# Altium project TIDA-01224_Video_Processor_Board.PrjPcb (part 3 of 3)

## Sheet TIDA-010224_Video_Processor_P04_Peripherals.SchDoc: TIDA-010224_P04_Peripherals
size A2; Date: Not shown in title block; ApprovedBy: Not shown in title block; CheckedBy: Not shown in title block; Author: Not shown in title block; CompanyName: Not shown in title block; DrawnBy: Sakshi Markhedkar; Engineer: Not shown in title block; Organization: Not shown in title block; Address1: Not shown in title block; Address2: Not shown in title block; Address3: Not shown in title block; Address4: Not shown in title block; DocumentNumber: 5; Revision: Use project parameter SCH_Rev; SheetNumber: 5; SheetTotal: 6; PageSetup: Record=PageOptions¦CenterHorizontal=True¦CenterVertical=True¦PrintScale=1.00¦XCorrection=1.00¦YCorrection=1.00¦PrintKind=0¦BorderSize=5000000¦LeftOffset=0¦BottomOffset=0¦Orientation=2¦PaperLength=1000¦PaperWidth=1000¦Scale=100¦PaperSource=15¦PrintQuality=600¦MediaType=1¦DitherType=10¦PaperKind=Letter¦PrintScaleMode=1
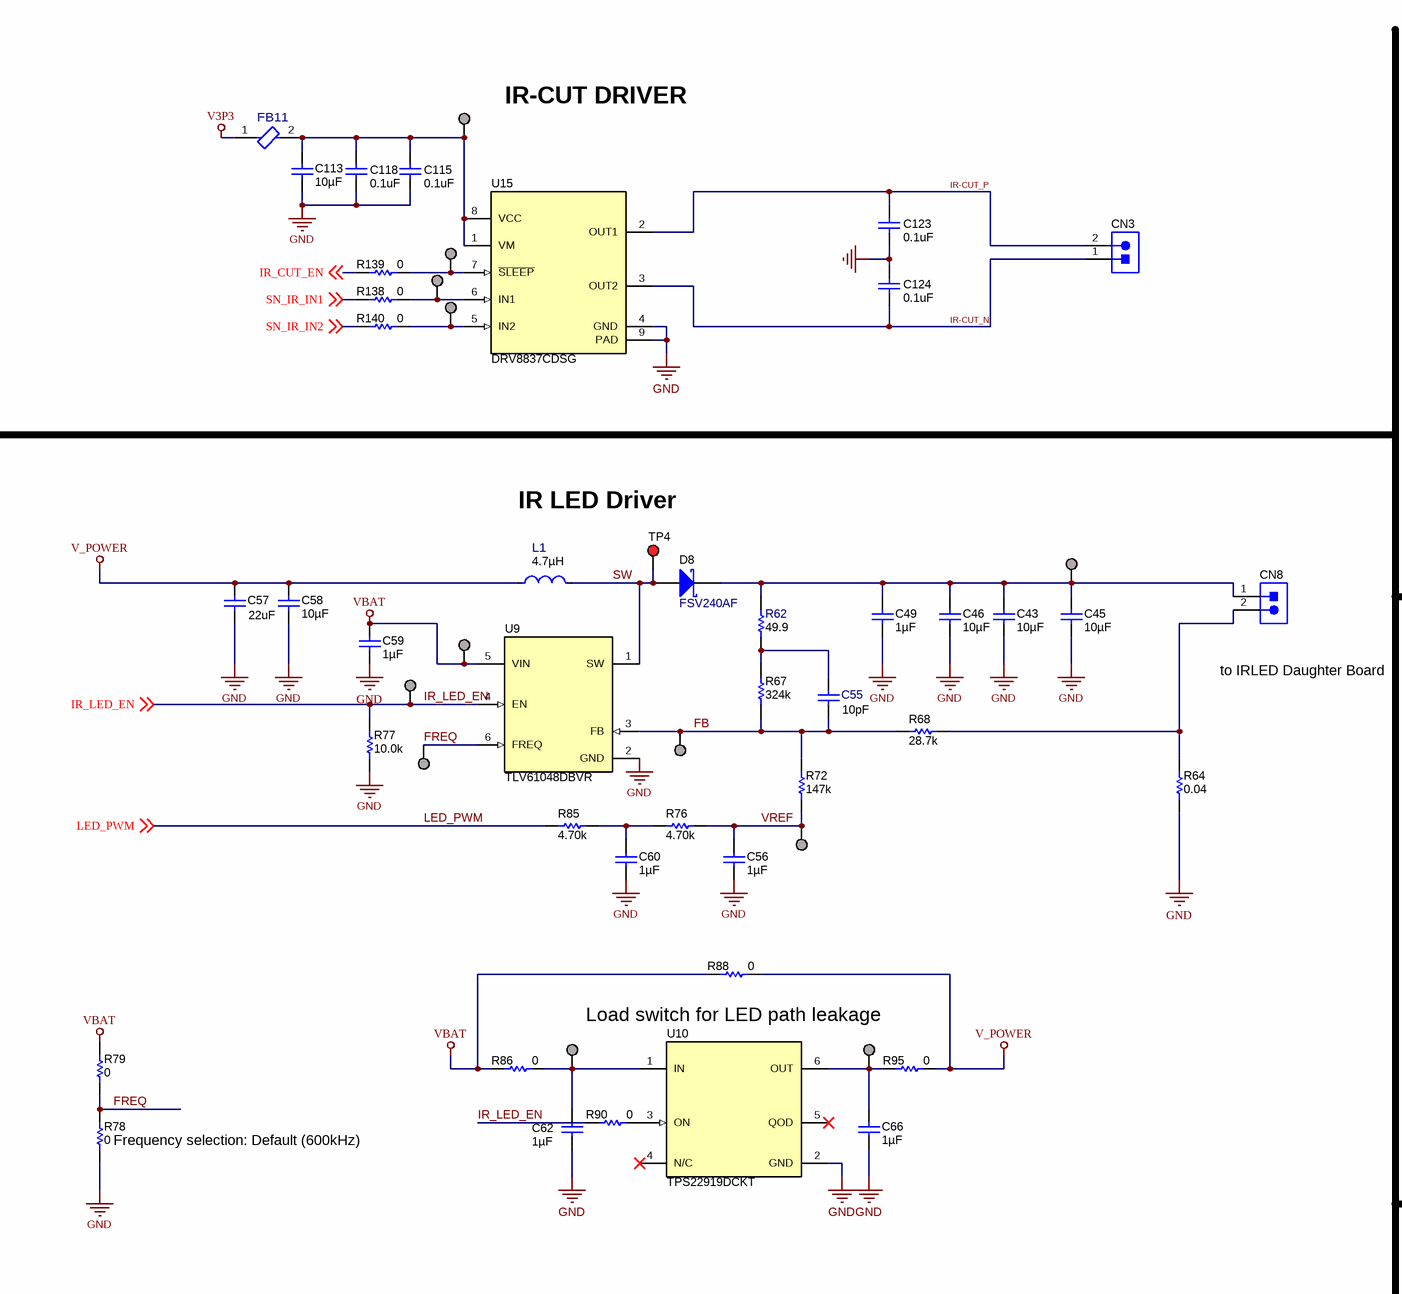
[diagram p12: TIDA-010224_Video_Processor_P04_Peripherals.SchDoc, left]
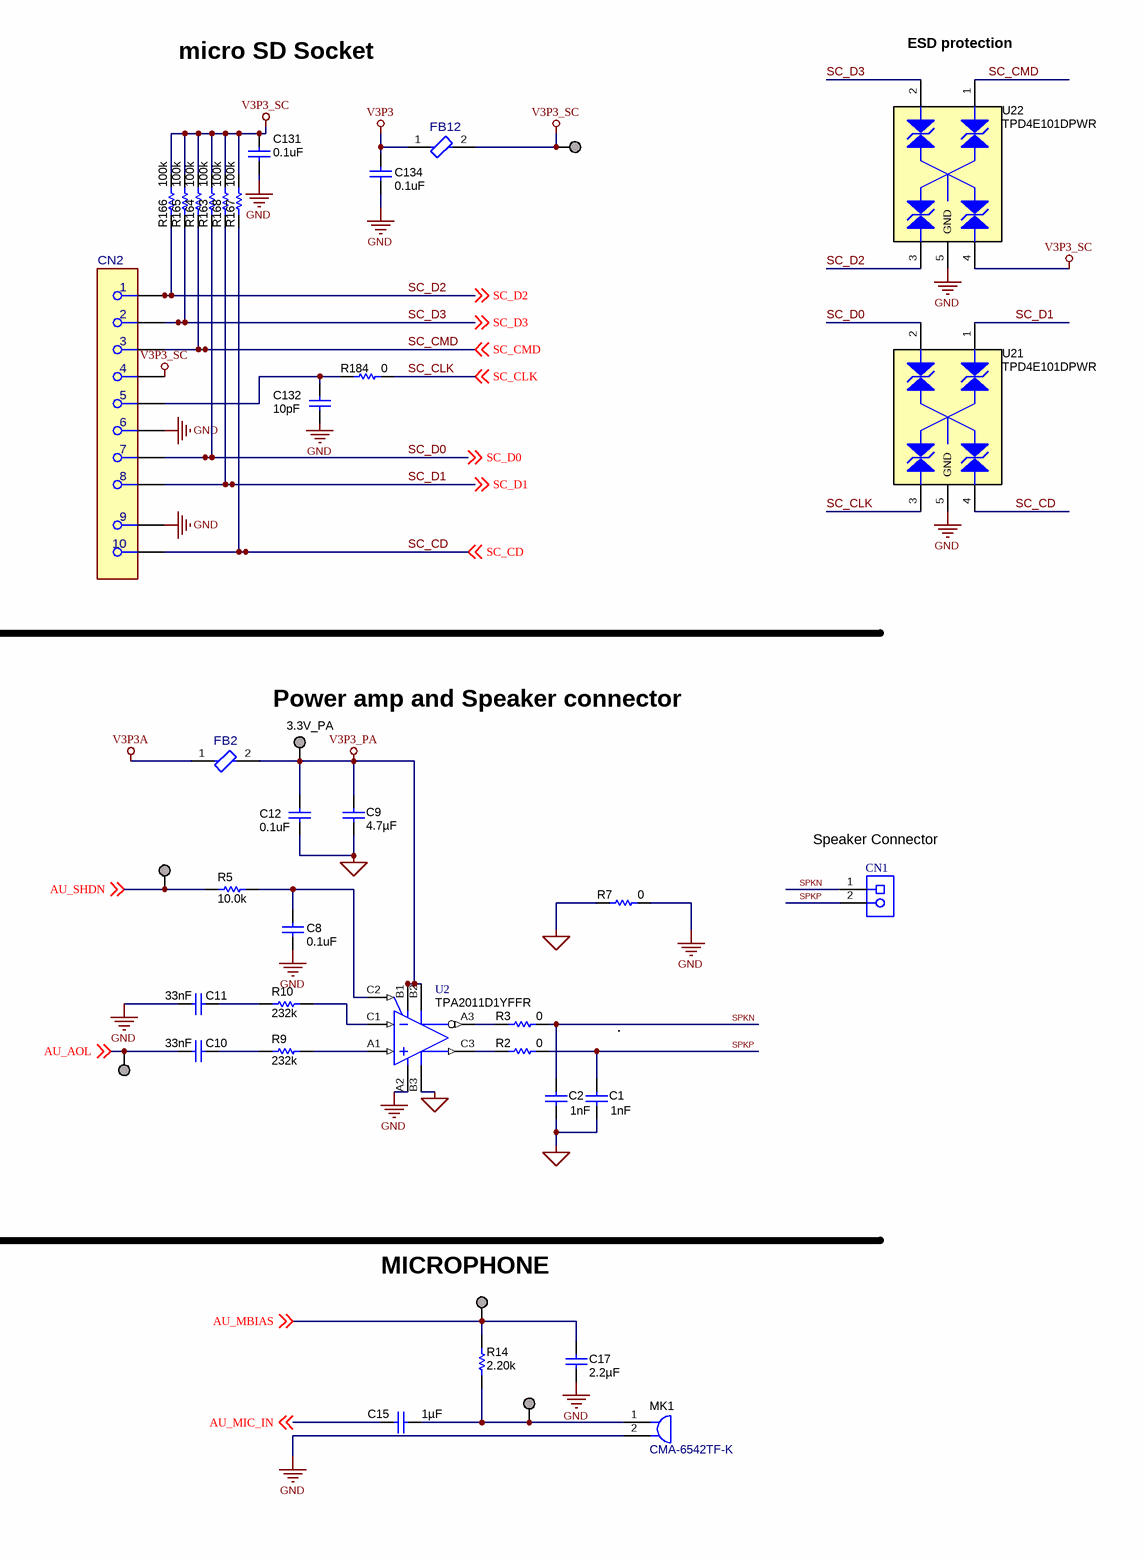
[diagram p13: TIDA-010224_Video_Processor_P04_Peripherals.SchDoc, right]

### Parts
3.3V_PA  RCU-0C  [TE_RCU]  (value not drawn)
3.3V_SC  TP_SM_1MM  [TP_SM_1MM]  (value not drawn)  (no BOM)
AOL  TP_SM_1MM  [TP_SM_1MM]  (value not drawn)  (no BOM)
C1  Cap_F: 1nF  [0402]  (hidden comment: GRM155R71C102KA01D)
C2  Cap_F: 1nF  [0402]  (hidden comment: GRM155R71C102KA01D)
C8  value 0.1uF  [0402]  (hidden comment: GRM155R71C104KA88D)
C9  Cap_F: 4.7µF  [0603]  (hidden comment: GRM188Z71C475KE21D)
C10  Cap_F: 33nF  [0402]  (hidden comment: GRM155R71C333KA01D)
C11  Cap_F: 33nF  [0402]  (hidden comment: GRM155R71C333KA01D)
C12  value 0.1uF  [0402]  (hidden comment: GRM155R71C104KA88D)
C15  Cap_F: 1µF  [0603]  (hidden comment: GCM188R71C105MA64D)
C17  Cap_F: 2.2µF  [0603]  (hidden comment: GRM188Z71C225KE43)
C43  Cap_F: 10µF  [0805_HV]  (hidden comment: CL21B106KOQNNNE)
C45  Cap_F: 10µF  [0805_HV]  (hidden comment: CL21B106KOQNNNE)
C46  Cap_F: 10µF  [0805_HV]  (hidden comment: CL21B106KOQNNNE)
C49  Cap_F: 1µF  [0603]  (hidden comment: GCM188R71C105MA64D)
C55  Cap_F: 10pF  [0402]  (hidden comment: GRM1555C1H100FA01D)
C56  Cap_F: 1µF  [0603]  (hidden comment: GCM188R71C105MA64D)
C57  ValueDisplayed: 22uF  [1210_280]  (hidden comment: CGA6P1X7R1C226M250AC)
C58  Cap_F: 10µF  [0805_HV]  (hidden comment: CL21B106KOQNNNE)
C59  Cap_F: 1µF  [0603]  (hidden comment: GCM188R71C105MA64D)
C60  Cap_F: 1µF  [0603]  (hidden comment: GCM188R71C105MA64D)
C62  Cap_F: 1µF  [0603]  (hidden comment: GCM188R71C105MA64D)
C66  Cap_F: 1µF  [0603]  (hidden comment: GCM188R71C105MA64D)
C113  Cap_F: 10µF  [0805_HV]  (hidden comment: CL21B106KOQNNNE)
C115  value 0.1uF  [0402]
C118  value 0.1uF  [0402]
C123  value 0.1uF  [0402]
C124  value 0.1uF  [0402]
C131  value 0.1uF  [0402]  (hidden comment: GRM155R71C104KA88D)
C132  ValueDisplayed: 10pF  [0402]  (hidden comment: 885012005055)
C134  value 0.1uF  [0402]  (hidden comment: GRM155R71C104KA88D)
CN1  282834-2  [TEC_282834-2]  (value not drawn)
CN2  693071010811  [FP-693071010811_CONN_SMT_MEMORY-MFG]  (value not drawn)
CN3  53398-0271  [0533980271]  (value not drawn)
CN8  PEC01DAAN  [Sullins_PxC01DAAN]  (value not drawn)
D8  FSV240AF  [SMAF]
FB  TP_SM_1MM  [TP_SM_1MM]  (value not drawn)  (no BOM)
FB2  BLM18KG121TN1D  [FP-BLM18KG121TN1D_0603-MFG]  (value not drawn)
FB11  BLM18KG121TN1D  [FP-BLM18KG121TN1D_0603-MFG]  (value not drawn)
FB12  BLM18KG121TN1D  [FP-BLM18KG121TN1D_0603-MFG]  (value not drawn)
FREQ  TP_SM_1MM  [TP_SM_1MM]  (value not drawn)  (no BOM)
IN_PS  TP_SM_1MM  [TP_SM_1MM]  (value not drawn)  (no BOM)
IR_EN  TP_SM_1MM  [TP_SM_1MM]  (value not drawn)  (no BOM)
IR_IN1  TP_SM_1MM  [TP_SM_1MM]  (value not drawn)  (no BOM)
IR_IN2  TP_SM_1MM  [TP_SM_1MM]  (value not drawn)  (no BOM)
L1  Ind_H: 4.7µH  [FP-XAL4030-472MEC_SMD2-MFG]  (hidden comment: XAL4030-472MEC)
LED_EN  TP_SM_1MM  [TP_SM_1MM]  (value not drawn)  (no BOM)
LED_OUT  TP_SM_1MM  [TP_SM_1MM]  (value not drawn)  (no BOM)
MBIAS  TP_SM_1MM  [TP_SM_1MM]  (value not drawn)  (no BOM)
MIC_IN  TP_SM_1MM  [TP_SM_1MM]  (value not drawn)  (no BOM)
MK1  CMA-6542TF-K  [CUI_CMA-6542TF-K]
OUT_PS  TP_SM_1MM  [TP_SM_1MM]  (value not drawn)  (no BOM)
R2  ValueDisplayed: 0  [0603]  (hidden comment: RMCF0603ZT0R00)
R3  ValueDisplayed: 0  [0603]  (hidden comment: RMCF0603ZT0R00)
R5  ValueDisplayed: 10.0k  [0402]  (hidden comment: ERJPA2F1002X)
R7  ValueDisplayed: 0  [0402S]  (hidden comment: RC0402JR-070RL)
R9  ValueDisplayed: 232k  [0402]  (hidden comment: RC1005F2323CS)
R10  ValueDisplayed: 232k  [0402]  (hidden comment: RC1005F2323CS)
R14  ValueDisplayed: 2.20k  [0402]  (hidden comment: ERA2AEB222X)
R62  ValueDisplayed: 49.9  [0603]  (hidden comment: CRCW060349R9FKEA)
R64  ValueDisplayed: 0.04  [2010]  (hidden comment: CSRN2010FK40L0)
R67  ValueDisplayed: 324k  [0603]  (hidden comment: RC0603FR-07324KL)
R68  ValueDisplayed: 28.7k  [0603]  (hidden comment: CRCW060328K7FKEA)
R72  ValueDisplayed: 147k  [0603]  (hidden comment: CRCW0603147KFKEA)
R76  ValueDisplayed: 4.70k  [0402]  (hidden comment: ERJ-2RKF4701X)
R77  ValueDisplayed: 10.0k  [0402]  (hidden comment: ERJPA2F1002X)
R78  ValueDisplayed: 0  [0402S]  (hidden comment: RC0402JR-070RL)
R79  ValueDisplayed: 0  [0402S]  (hidden comment: RC0402JR-070RL)
R85  ValueDisplayed: 4.70k  [0402]  (hidden comment: ERJ-2RKF4701X)
R86  ValueDisplayed: 0  [0603]  (hidden comment: RMCF0603ZT0R00)
R88  ValueDisplayed: 0  [0603]  (hidden comment: RMCF0603ZT0R00)
R90  ValueDisplayed: 0  [0402S]  (hidden comment: RC0402JR-070RL)
R95  ValueDisplayed: 0  [0603]  (hidden comment: RMCF0603ZT0R00)
R138  ValueDisplayed: 0  [0402S]  (hidden comment: RC0402JR-070RL)
R139  ValueDisplayed: 0  [0402S]  (hidden comment: RC0402JR-070RL)
R140  ValueDisplayed: 0  [0402S]  (hidden comment: RC0402JR-070RL)
R163  ValueDisplayed: 100k  [0201]  (hidden comment: RC0201FR-07100KL)
R164  ValueDisplayed: 100k  [0201]  (hidden comment: RC0201FR-07100KL)
R165  ValueDisplayed: 100k  [0201]  (hidden comment: RC0201FR-07100KL)
R166  ValueDisplayed: 100k  [0201]  (hidden comment: RC0201FR-07100KL)
R167  ValueDisplayed: 100k  [0201]  (hidden comment: RC0201FR-07100KL)
R168  ValueDisplayed: 100k  [0201]  (hidden comment: RC0201FR-07100KL)
R184  ValueDisplayed: 0  [0402S]  (hidden comment: RC0402JR-070RL)
REF  TP_SM_1MM  [TP_SM_1MM]  (value not drawn)  (no BOM)
SHDN  TP_SM_1MM  [TP_SM_1MM]  (value not drawn)  (no BOM)
TP4  Bias  [Keystone5000]  (value not drawn)
U2  TPA2011D1YFFR  [YFF0009AAAC]
U9  TLV61048DBVR  [DBV0006A_N]
U10  TPS22919DCKT  [DCK0006A_N]
U15  DRV8837CDSG  [DSG0008A]
U21  TPD4E101DPWR  [DPW0004A]
U22  TPD4E101DPWR  [DPW0004A]
VCC_IR  TP_SM_1MM  [TP_SM_1MM]  (value not drawn)  (no BOM)
VP  TP_SM_1MM  [TP_SM_1MM]  (value not drawn)  (no BOM)

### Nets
AGND: C1.2 C2.2 C9.2 C12.1 R7.1 U2.B3(PGND)
GND: C8.1 C11.2 C17.1 C43.2 C45.2 C46.2 C49.1 C56.1 C57.2 C58.2 C59.1 C60.1 C62.2 C66.2 C113.2 C115.1 C118.1 C123.1 C124.2 C131.1 C132.2 C134.1 CN2.6 CN2.9 MK1.2 R7.2 R64.1 R77.1 R78.1 U2.A2(GND) U9.2(GND) U10.2(GND) U15.4(GND) U15.9(PAD) U21.5(GND) U22.5(GND)
V3P3: C134.2 FB11.1 FB12.1
V3P3_PA: 3.3V_PA.1 C9.1 C12.2 FB2.2 U2.B1(VDD) U2.B2(PVDD)
V3P3_SC: 3.3V_SC.1 C131.2 CN2.4 FB12.2 R163.2 R164.2 R165.2 R166.2 R167.2 R168.2 U22.4
V3P3A: FB2.1
V_POWER: C57.1 C58.1 L1.1 R88.2 R95.2
VBAT: C59.2 R79.2 R86.1 R88.1 U9.5(VIN) VP.1
AU_AOL: AOL.1 C10.2 ; off-sheet AU_AOL
AU_MBIAS: C17.2 MBIAS.1 R14.2 ; off-sheet AU_MBIAS
AU_MIC_IN: C15.1 ; off-sheet AU_MIC_IN
AU_SHDN: R5.1 SHDN.1 ; off-sheet AU_SHDN
FB: C55.2 FB.1 R67.1 R68.1 R72.2 U9.3(FB)
FREQ: FREQ.1 R78.2 R79.1 U9.6(FREQ)
IR-CUT_N: C124.1 CN3.1 U15.3(OUT2)
IR-CUT_P: C123.2 CN3.2 U15.2(OUT1)
IR_CUT_EN: R139.1 ; off-sheet IR_CUT_EN
IR_LED_EN: LED_EN.1 R77.2 R90.1 U9.4(EN) ; off-sheet IR_LED_EN
LED_PWM: R85.1 ; off-sheet LED_PWM
SC_CD: CN2.10 R167.1 U21.4 ; off-sheet SC_CD
SC_CLK: R184.2 U21.3 ; off-sheet SC_CLK
SC_CMD: CN2.3 R164.1 U22.1 ; off-sheet SC_CMD
SC_D0: CN2.7 R163.1 U21.2 ; off-sheet SC_D0
SC_D1: CN2.8 R168.1 U21.1 ; off-sheet SC_D1
SC_D2: CN2.1 R166.1 U22.3 ; off-sheet SC_D2
SC_D3: CN2.2 R165.1 U22.2 ; off-sheet SC_D3
SN_IR_IN1: R138.1 ; off-sheet SN_IR_IN1
SN_IR_IN2: R140.1 ; off-sheet SN_IR_IN2
SPKN: C2.1 CN1.1 R3.2
SPKP: C1.1 CN1.2 R2.2
SW: D8.2(A) L1.2 TP4.1 U9.1(SW)
VREF: C56.2 R72.1 R76.2 REF.1
NetC8_2: C8.2 R5.2 U2.C2(EN)
NetC10_1: C10.1 R9.1
NetC11_1: C11.1 R10.1
NetC15_2: C15.2 MIC_IN.1 MK1.1 R14.1
NetC43_1: C43.1 C45.1 C46.1 C49.2 CN8.1 D8.1(K) LED_OUT.1 R62.2
NetC55_1: C55.1 R62.1 R67.2
NetC60_2: C60.2 R76.1 R85.2
NetC62_1: C62.1 IN_PS.1 R86.2 U10.1(IN)
NetC66_1: C66.1 OUT_PS.1 R95.1 U10.6(OUT)
NetC113_1: C113.1 C115.2 C118.2 FB11.2 U15.1(VM) U15.8(VCC) VCC_IR.1
NetC132_1: C132.1 CN2.5 R184.1
NetCN8_2: CN8.2 R64.2 R68.2
NetIR_EN_1: IR_EN.1 R139.2 U15.7(~{SLEEP})
NetIR_IN1_1: IR_IN1.1 R138.2 U15.6(IN1)
NetIR_IN2_1: IR_IN2.1 R140.2 U15.5(IN2)
NetR2_1: R2.1 U2.C3(VO+)
NetR3_1: R3.1 U2.A3(VO-)
NetR9_2: R9.2 U2.A1(IN+)
NetR10_2: R10.2 U2.C1(IN-)
NetR90_2: R90.2 U10.3(ON)

Not connected (* = marked no-connect by the designer): U10 4(N/C)* 5(QOD)*

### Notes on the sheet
- micro SD Socket
- ESD protection
- (near VCC_IR) IR-CUT DRIVER
- (near TP4) IR LED Driver
- to IRLED Daughter Board
- (near 3.3V_PA) Power amp and Speaker connector
- (near CN1) Speaker Connector
- Load switch for LED path leakage
- (near R78) Frequency selection: Default (600kHz)
- (near MBIAS) MICROPHONE

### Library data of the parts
3.3V_PA = CMP-0067620-1: PC Test Point, SMT; Manufacturer: TE Connectivity
3.3V_SC AOL FB FREQ IN_PS IR_EN IR_IN1 IR_IN2 LED_EN LED_OUT MBIAS MIC_IN OUT_PS REF SHDN VCC_IR VP = CMP-0003825-1: 1mm Test Point, SMT; Manufacturer: Any
C1 C2 = CMP-0006638-2: CAP, CERM, 1000 pF, 16 V, +/- 10%, X7R, 0402; Manufacturer: MuRata; TaMin_C: -55°C; Polarized: N; SizeAreaWB_mm2: 3; Value1: Unknown; U/M: EA; Value: 1000pF; TaMax_C: 125°C; SizeZ_mm: 0.6; SizeX_mm: 1; SizeY_mm: 0.5; Value2: 16V; AEC Category: Q200
C8 C12 C131 C134 = Cap: CAP CER 0.1UF 16V 10% X7R 0402; Manufacturer: Murata Electronics North America
C9 = CMP-0064936-4: CAP, CERM, 4.7 uF, 16 V,+/- 10%, X7R, 0603; Manufacturer: MuRata; TaMin_C: -55°C; Polarized: N; SizeAreaWB_mm2: 4.68; Value1: Unknown; U/M: EA; Value: 4.7uF; TaMax_C: 125°C; SizeZ_mm: 1; SizeX_mm: 1.6; SizeY_mm: 0.8; Value2: 16V; SizeArea_mm2: 1.28; AEC Category: Q200
C10 C11 = CMP-0006650-2: CAP, CERM, 0.033 uF, 16 V, +/- 10%, X7R, 0402; Manufacturer: MuRata; TaMin_C: -55°C; Polarized: N; SizeAreaWB_mm2: 3; Value1: Unknown; U/M: EA; TaMax_C: 125°C; SizeZ_mm: 0.6; SizeX_mm: 1; SizeY_mm: 0.5; Value2: 16V; AEC Category: Q200
C15 C49 C56 C59 C60 C62 C66 = CMP-0007137-1: CAP, CERM, 1 uF, 16 V, +/- 20%, X7R, AEC-Q200 Grade 1, 0603; Manufacturer: MuRata; TaMin_C: -55°C; Polarized: N; SizeAreaWB_mm2: 4.68; Value1: Unknown; U/M: EA; Value: 1uF; TaMax_C: 125°C; SizeZ_mm: 1; SizeX_mm: 1.6; SizeY_mm: 0.8; Value2: 16V; SizeArea_mm2: 1.28; AEC Qualified: Y; AEC Category: Q200
C17 = CMP-0007499-1: CAP, CERM, 2.2 uF, 16 V, +/- 10%, X7R, 0603; Manufacturer: MuRata; TaMin_C: -55°C; Polarized: N; SizeAreaWB_mm2: 4.68; Value1: Unknown; U/M: EA; Value: 2.2uF; TaMax_C: 125°C; SizeZ_mm: 1; SizeX_mm: 1.6; SizeY_mm: 0.8; Value2: 16V; SizeArea_mm2: 1.28; AEC Category: Q200
C43 C45 C46 C58 C113 = CMP-0007995-1: CAP, CERM, 10 uF, 16 V, +/- 10%, X7R, 0805; Manufacturer: Samsung Electro-Mechanics; TaMin_C: -55°C; Polarized: N; SizeAreaWB_mm2: 6.75; Value1: Unknown; U/M: EA; Value: 10uF; TaMax_C: 125°C; SizeZ_mm: 1.45; SizeX_mm: 2; SizeY_mm: 1.25; Cap_Case: 0805; Value2: 16V; SizeArea_mm2: 2.5; AEC Category: Q200
C55 = CMP-0064916-2: CAP, CERM, 10 pF, 50 V,+/- 1%, C0G/NP0, 0402; Manufacturer: MuRata; TaMin_C: -55°C; Polarized: N; SizeAreaWB_mm2: 3; Value1: Unknown; U/M: EA; Value: 10pF; TaMax_C: 125°C; SizeZ_mm: 0.6; SizeX_mm: 1; SizeY_mm: 0.5; Value2: 50V; AEC Category: Q200
C57 = CMP-0009154-2: CAP, CERM, 22 uF, 16 V, +/- 20%, X7R, AEC-Q200 Grade 1, 1210; Manufacturer: TDK; TaMin_C: -55°C; ESR_ohm: 2.582m; Polarized: N; SizeAreaWB_mm2: 14.7; Value1: 0.002582 ohm; U/M: EA; Value: 22uF; TaMax_C: 125°C; SizeZ_mm: 2.8; SizeX_mm: 3.2; SizeY_mm: 2.5; Value2: 16V; SizeArea_mm2: 8; AEC Qualified: Y; Cap_F: 22µF; IRMS_A: 4.57562A; AEC Grade: 1; AEC Category: Q200
C115 C118 C123 C124 = Cap: CAP CER 0.1UF 16V 10% X7R 0402; Manufacturer: Murata Electronics North America; MFG Part Number: GRM155R71C104KA88D
C132 = CMP-0006215-2: CAP, CERM, 10 pF, 50 V, +/- 5%, C0G/NP0, 0402; Manufacturer: Wurth Elektronik; TaMin_C: -55°C; Polarized: N; SizeAreaWB_mm2: 3; Value1: Unknown; U/M: EA; Value: 10pF; TaMax_C: 125°C; SizeZ_mm: 0.6; SizeX_mm: 1; SizeY_mm: 0.5; Value2: 50V; AEC Category: Q200
CN1 = CMP-0054974-1: Terminal Block, 2x1, 2.54mm, TH; Manufacturer: TE Connectivity; CNHeader: FALSE; Green_Lifecycle: Active; Green_REACh: Passed; CT: TRUE
CN2 = CMP-0089421-1: 9 (8 + 1) Position Card Connector Secure Digital - microSD™ Surface Mount, Right Angle Gold; Manufacturer: Wurth Electronics; DUT-Pitch_mm: 1.1mm; Conn Orientation: Horizontal; Is Female: yes; AEC Qualified: No; Voltage_V: 100V; SizeZ_mm: 2.13mm; Memory Type: FLASH; Current_A: 500mA
CN3 = CMP-0055117-1: Plug, SMT, Vertical, 1.25mm, 1x2; Manufacturer: Molex; CT: FALSE; CompType: Header
CN8 = CMP-0054594-1: Header, 2.54mm, 1x2, Tin, Black, TH; Manufacturer: Sullins Connector Solutions; CNHeader: TRUE; Current_A: 3A; Green_Lifecycle: Active; Shrouded: N; Gender: Male; Green_REACh: Passed; Voltage_V: 1.8kV; Row_Count: 2; RowSpacing_mm: 2.54; CT: FALSE; Cert_UL: Y
D8 = CMP-0028822-2: Diode, Schottky, 40 V, 2 A, AEC-Q101, SMAF; Manufacturer: Fairchild Semiconductor; AEC Category: Q101; SizeArea_mm2: 11.75; Vr_V: 40V; TJmax_C: 150°C; SizeY_mm: 2.5; Green_REACh: Incomplete; Io_A: 2A; SizeX_mm: 4.7; AEC Qualified: Y; Green_Lifecycle: Not Set; Value: 40V; SizeAreaWB_mm2: 19.95; Vf_V: 500mV; Value2: 0.5V; SizeZ_mm: 1
FB2 FB11 FB12 = CMP-0089995-1: 120 Ohms @ 100MHz 1 Power Line Ferrite Bead 0603 (1608 Metric) 3A 30mOhm; Manufacturer: Murata; DCR_ohm: 0.03; Impedance At Frequency: 120Ω @ 100MHz; Tolerance_%: 25%; AEC Qualified: No; SizeZ_mm: 0.75mm
L1 = CMP-0089502-1: Power Inductor (SMD), 4.7 µH, 5.1 A, Shielded, 4.5 A, XAL40xx Series, 4mm x 4mm x 3.1mm; Manufacturer: Coilcraft; Material: Composite; TaMin_C: -40°C; Test Frequency: 1MHz; Shrouded: true; Irms: 5.1A; AEC Grade: Grade 1; Tolerance_%: 20%; Isat: 4.5A; AEC Qualified: Yes; Standoff Height: 0.08mm; DCR_ohm: 0.0441; Self Resonant Frequency: 36MHz; TaMax_C: +125°C
MK1 = CMP-0001813-2: Microphone, Electret Condenser, Omnidirectional, -42 dB, SMD; Manufacturer: CUI Inc.
R2 R3 = CMP-0023343-3: RES, 0, 1%, 0.1 W, AEC-Q200 Grade 0, 0603; Manufacturer: Stackpole Electronics Inc; Power_W: 100mW; TempCo: ppm/C; U/M: EA; Value: 0; SizeX_mm: 1.6; SizeY_mm: 0.8; SizeZ_mm: 1; Value2: 0.1W; SizeArea_mm2: 1.28; AEC Qualified: Y; AEC Category: Q200
R5 R77 = CMP-0078779-1: RES, 10.0 k, 1%, 0.2 W, AEC-Q200 Grade 0, 0402; Manufacturer: Panasonic; Value_Code: 10k0; SizeArea_mm2: 0.5; AEC Qualified: Y; AEC Category: Q200; Res_ohm: 10k; Value: 10.0k; SizeZ_mm: 0.6; EIA_Code: E96; TempCo: 100 ppm/C; AEC Grade: 0; Power_W: 200mW; VDC_V: 50V; Value2: 0.2W; SizeX_mm: 1
R7 R78 R79 R90 R138-R140 R184 = CMP-0027004-2: RES, 0, 5%, 0.063 W, 0402; Manufacturer: Yageo America; Power_W: 63mW; TempCo: 200 ppm/C; Value_Code: 0000; U/M: EA; Value: 0; EIA_Code: E24; SizeX_mm: 1; SizeY_mm: 0.5; SizeZ_mm: 0.6; Value2: 0.063W; VDC_V: 50V; AEC Category: Q200
R9 R10 = CMP-0026746-1: RES, 232 k, 1%, 0.063 W, 0402; Manufacturer: Samsung Electro-Mechanics; Power_W: 63mW; TempCo: 100 ppm/C; U/M: EA; Value: 232k; EIA_Code: E96; SizeX_mm: 1; SizeY_mm: 0.5; SizeZ_mm: 0.6; Value2: 0.063W; AEC Qualified: N; VDC_V: 50V; AEC Category: Q200
R14 = CMP-0074667-1: RES, 2.20 k, 0.1%, 0.0625 W, AEC-Q200 Grade 0, 0402; Manufacturer: Panasonic; Power_W: 62.5mW; TempCo: 25 ppm/C; Value_Code: 2k20; U/M: EA; Value: 2.20k; Res_ohm: 2.2k; SizeX_mm: 1.0; SizeY_mm: 0.5; SizeZ_mm: 0.6; AEC Qualified: Y; VDC_V: 50V; AEC Grade: 0; AEC Category: Q200
R62 = CMP-0022448-4: RES, 49.9, 1%, 0.1 W, AEC-Q200 Grade 0, 0603; Manufacturer: Vishay-Dale; Power_W: 100mW; TempCo: 100 ppm/C; Value_Code: 49R9; Value: 49.9; EIA_Code: E96; SizeX_mm: 1.6; SizeY_mm: 0.8; SizeZ_mm: 1; Value2: 0.1W; SizeArea_mm2: 1.28; AEC Qualified: Y; VDC_V: 75V; AEC Category: Q200; AEC Grade: 0
R64 = CMP-0016519-2: RES, 0.04, 1%, 1 W, 2010; Manufacturer: Stackpole Electronics Inc; Power_W: 1W; TempCo: 250 ppm/C; Value_Code: R040; U/M: EA; Value: 0.04; SizeX_mm: 5; SizeY_mm: 2.5; SizeZ_mm: 1.66; SizeArea_mm2: 12.5; AEC Category: Q200
R67 = CMP-0023028-4: RES, 324 k, 1%, 0.1 W, 0603; Manufacturer: Yageo; Power_W: 100mW; TempCo: 100 ppm/C; Value: 324k; EIA_Code: E96; SizeX_mm: 1.6; SizeY_mm: 0.8; SizeZ_mm: 1; Value2: 0.1W; SizeArea_mm2: 1.28; AEC Qualified: N; VDC_V: 75V; AEC Category: Q200; SizeAreaWB_mm2: 4.68
R68 = CMP-0022261-4: RES, 28.7 k, 1%, 0.1 W, AEC-Q200 Grade 0, 0603; Manufacturer: Vishay-Dale; Power_W: 100mW; TempCo: 100 ppm/C; Value_Code: 28k7; Value: 28.7k; EIA_Code: E96; SizeX_mm: 1.6; SizeY_mm: 0.8; SizeZ_mm: 1; Value2: 0.1W; SizeArea_mm2: 1.28; AEC Qualified: Y; VDC_V: 75V; AEC Category: Q200; AEC Grade: 0
R72 = CMP-0022052-4: RES, 147 k, 1%, 0.1 W, AEC-Q200 Grade 0, 0603; Manufacturer: Vishay-Dale; Power_W: 100mW; TempCo: 100 ppm/C; Value: 147k; EIA_Code: E96; SizeX_mm: 1.6; SizeY_mm: 0.8; SizeZ_mm: 1; Value2: 0.1W; SizeArea_mm2: 1.28; AEC Qualified: Y; VDC_V: 75V; AEC Category: Q200; AEC Grade: 0
R76 R85 = CMP-0026700-1: RES, 4.70 k, 1%, 0.1 W, 0402; Manufacturer: Panasonic; Power_W: 100mW; TempCo: 100 ppm/C; Value_Code: 4k70; U/M: EA; Value: 4.70k; Res_ohm: 4.7k; SizeX_mm: 1; SizeY_mm: 0.5; SizeZ_mm: 0.6; Value2: 0.1W; VDC_V: 50V; AEC Category: Q200
R86 R88 R95 = CMP-0023343-2: RES, 0, 1%, 0.1 W, AEC-Q200 Grade 0, 0603; Manufacturer: Stackpole Electronics Inc; Power_W: 100mW; TempCo: ppm/C; U/M: EA; Value: 0; SizeX_mm: 1.6; SizeY_mm: 0.8; SizeZ_mm: 1; Value2: 0.1W; SizeArea_mm2: 1.28; AEC Qualified: Y; AEC Category: Q200
R163-R168 = CMP-0027293-2: RES, 100 k, 1%, 0.05 W, 0201; Manufacturer: Yageo America; Power_W: 50mW; TempCo: 200 ppm/C; U/M: EA; Value: 100k; EIA_Code: E96; SizeX_mm: 0.6; SizeY_mm: 0.3; SizeZ_mm: 0.26; Value2: 0.05W; SizeArea_mm2: 0.18; AEC Qualified: N; VDC_V: 25V; AEC Category: Q200
TP4 = CMP-0055137-1: Test Point, Miniature, Red, TH; Manufacturer: Keystone; CNHeader: FALSE; Green_Lifecycle: Active; Green_REACh: Passed; ContactFinish: Silver; CT: TRUE
U2 = CMP-0042983-1: 3.2 W Mono Class-D With Auto-Recovering Short-Circuit Protection, -40 to 85 degC, 9-pin BGA (YFF9), Green (RoHS & no Sb/Br); Manufacturer: Texas Instruments; Output Power(W): 3.24; PSRR(dB): 86; Supply Min(Min)(Volt): 2.5; SubFamily: Dynamic Speaker; Supply Max(Max)(Volt): 5.5
U9 = CMP-0085596-1: 15-V Output Voltage Non-Sync Boost Converter, DBV0006A (SOT-23-6); Alternate PartNumber: TLV61048DBVT; Alternate Manufacturer: Texas Instruments; SizeY_mm: 2.9; AEC Qualified: N; SizeArea_mm2: 8.12; SizeZ_mm: 1.45; SizeX_mm: 2.8; SizeAreaWB_mm2: 14.82; AEC Category: Q200; CompType: IC
U10 = CMP-0081107-1: 5.5-V, 1.5-A, 100-mohm Load Switch with Output Discharge, DCK0006A (SOT-SC70-6); Alternate PartNumber: TPS22919DCKR; Alternate Manufacturer: Texas Instruments; SizeAreaWB_mm2: 9.3; SizeZ_mm: 1.1; SizeX_mm: 2.1; SizeY_mm: 2; SizeArea_mm2: 4.2; CompType: IC; AEC Qualified: N; AEC Category: Q200
U15 = CMP-0013449-3: 1-A Low-Voltage H-Bridge Driver, DSG0008A (WSON-8); Manufacturer: Texas Instruments; SizeZ_mm: 0.8; SizeX_mm: 2; SizeArea_mm2: 4; CompType: IC; U/M: EA; SizeAreaWB_mm2: 9
U21 U22 = CMP-0066604-2: 4-Channel ESD Protection With +/-15kV Contact ESD, DPW0004A (X2SON-4); Manufacturer: Texas Instruments; SizeZ_mm: 0.4; SizeX_mm: 0.8; SizeArea_mm2: 0.64; CompType: IC; U/M: EA; SizeAreaWB_mm2: 3.24

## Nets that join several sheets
GND: TIDA-010224_Video_Processor_P01_Power_Delivery (75 pins), TIDA-010224_Video_Processor_P02_OA7000_Image_Sensor (115 pins), TIDA-010224_Video_Processor_P03_CC3235MODA_WIFI_Launchpad (58 pins), TIDA-010224_Video_Processor_P04_Peripherals (36 pins)
V1P1: TIDA-010224_Video_Processor_P01_Power_Delivery (J14.1), TIDA-010224_Video_Processor_P02_OA7000_Image_Sensor (FB7.1)
V1P8: TIDA-010224_Video_Processor_P01_Power_Delivery (J12.1 R105.2), TIDA-010224_Video_Processor_P02_OA7000_Image_Sensor (C40.1 CN9.4 FB4.1 FB10.1)
V1P35: TIDA-010224_Video_Processor_P01_Power_Delivery (J6.1), TIDA-010224_Video_Processor_P02_OA7000_Image_Sensor (FB5.1)
V3P3: TIDA-010224_Video_Processor_P01_Power_Delivery (J2.1), TIDA-010224_Video_Processor_P02_OA7000_Image_Sensor (5 pins), TIDA-010224_Video_Processor_P04_Peripherals (C134.2 FB11.1 FB12.1)
V3P3A: TIDA-010224_Video_Processor_P01_Power_Delivery (7 pins), TIDA-010224_Video_Processor_P03_CC3235MODA_WIFI_Launchpad (FB1.1), TIDA-010224_Video_Processor_P04_Peripherals (FB2.1)
VBAT: TIDA-010224_Video_Processor_P01_Power_Delivery (16 pins), TIDA-010224_Video_Processor_P04_Peripherals (6 pins)
VEFUSE: TIDA-010224_Video_Processor_P01_Power_Delivery (R42.2), TIDA-010224_Video_Processor_P02_OA7000_Image_Sensor (C33.1 CN6.H9 R132.2 VeFuse.1)
AU_AOL: TIDA-010224_Video_Processor_P02_OA7000_Image_Sensor (CN6.N10), TIDA-010224_Video_Processor_P04_Peripherals (AOL.1 C10.2)
AU_MBIAS: TIDA-010224_Video_Processor_P02_OA7000_Image_Sensor (CN6.N13), TIDA-010224_Video_Processor_P04_Peripherals (C17.2 MBIAS.1 R14.2)
AU_MIC_IN: TIDA-010224_Video_Processor_P02_OA7000_Image_Sensor (CN6.N12), TIDA-010224_Video_Processor_P04_Peripherals (C15.1)
AU_SHDN: TIDA-010224_Video_Processor_P02_OA7000_Image_Sensor (CN6.A9), TIDA-010224_Video_Processor_P04_Peripherals (R5.1 SHDN.1)
EFUSE_SW: TIDA-010224_Video_Processor_P01_Power_Delivery (EN.1 U7.3), TIDA-010224_Video_Processor_P02_OA7000_Image_Sensor (CN6.J9)
HOST_ON: TIDA-010224_Video_Processor_P01_Power_Delivery (R129.2 R131.2), TIDA-010224_Video_Processor_P03_CC3235MODA_WIFI_Launchpad (R51.1 R160.2)
IR_CUT_EN: TIDA-010224_Video_Processor_P02_OA7000_Image_Sensor (R125.2 R143.1), TIDA-010224_Video_Processor_P03_CC3235MODA_WIFI_Launchpad (R159.2), TIDA-010224_Video_Processor_P04_Peripherals (R139.1)
IR_LED_EN: TIDA-010224_Video_Processor_P03_CC3235MODA_WIFI_Launchpad (R176.2), TIDA-010224_Video_Processor_P04_Peripherals (LED_EN.1 R77.2 R90.1 U9.4)
LED_PWM: TIDA-010224_Video_Processor_P02_OA7000_Image_Sensor (R46.1), TIDA-010224_Video_Processor_P03_CC3235MODA_WIFI_Launchpad (R17.2), TIDA-010224_Video_Processor_P04_Peripherals (R85.1)
RDY: TIDA-010224_Video_Processor_P02_OA7000_Image_Sensor (CN6.F13), TIDA-010224_Video_Processor_P03_CC3235MODA_WIFI_Launchpad (R25.2 R39.2 R50.2)
SC_CD: TIDA-010224_Video_Processor_P02_OA7000_Image_Sensor (CN6.K3), TIDA-010224_Video_Processor_P04_Peripherals (CN2.10 R167.1 U21.4)
SC_CLK: TIDA-010224_Video_Processor_P02_OA7000_Image_Sensor (CN6.J1), TIDA-010224_Video_Processor_P04_Peripherals (R184.2 U21.3)
SC_CMD: TIDA-010224_Video_Processor_P02_OA7000_Image_Sensor (CN6.J2), TIDA-010224_Video_Processor_P04_Peripherals (CN2.3 R164.1 U22.1)
SC_D0: TIDA-010224_Video_Processor_P02_OA7000_Image_Sensor (CN6.H1), TIDA-010224_Video_Processor_P04_Peripherals (CN2.7 R163.1 U21.2)
SC_D1: TIDA-010224_Video_Processor_P02_OA7000_Image_Sensor (CN6.H2), TIDA-010224_Video_Processor_P04_Peripherals (CN2.8 R168.1 U21.1)
SC_D2: TIDA-010224_Video_Processor_P02_OA7000_Image_Sensor (CN6.K2), TIDA-010224_Video_Processor_P04_Peripherals (CN2.1 R166.1 U22.3)
SC_D3: TIDA-010224_Video_Processor_P02_OA7000_Image_Sensor (CN6.K1), TIDA-010224_Video_Processor_P04_Peripherals (CN2.2 R165.1 U22.2)
SN_IR_IN1: TIDA-010224_Video_Processor_P02_OA7000_Image_Sensor (R23.1 R130.1), TIDA-010224_Video_Processor_P03_CC3235MODA_WIFI_Launchpad (R156.2), TIDA-010224_Video_Processor_P04_Peripherals (R138.1)
SN_IR_IN2: TIDA-010224_Video_Processor_P02_OA7000_Image_Sensor (R24.1 R45.1), TIDA-010224_Video_Processor_P03_CC3235MODA_WIFI_Launchpad (R155.2), TIDA-010224_Video_Processor_P04_Peripherals (R140.1)
SPI_CLK: TIDA-010224_Video_Processor_P02_OA7000_Image_Sensor (CN6.A13), TIDA-010224_Video_Processor_P03_CC3235MODA_WIFI_Launchpad (R29.2 R36.2 R58.1)
SPI_CS: TIDA-010224_Video_Processor_P02_OA7000_Image_Sensor (CN6.B13), TIDA-010224_Video_Processor_P03_CC3235MODA_WIFI_Launchpad (R27.2 R35.2 R71.2)
SPI_MISO: TIDA-010224_Video_Processor_P02_OA7000_Image_Sensor (CN6.C13), TIDA-010224_Video_Processor_P03_CC3235MODA_WIFI_Launchpad (R37.2 R54.2 R121.2)
SPI_MOSI: TIDA-010224_Video_Processor_P02_OA7000_Image_Sensor (CN6.C12), TIDA-010224_Video_Processor_P03_CC3235MODA_WIFI_Launchpad (R28.2 R38.2 R59.2)
SYNC: TIDA-010224_Video_Processor_P02_OA7000_Image_Sensor (CN6.D13), TIDA-010224_Video_Processor_P03_CC3235MODA_WIFI_Launchpad (R26.2 R40.2 R48.2)
USB_DN: TIDA-010224_Video_Processor_P01_Power_Delivery (CN5.2 U8.3), TIDA-010224_Video_Processor_P02_OA7000_Image_Sensor (CN6.F1)
USB_DP: TIDA-010224_Video_Processor_P01_Power_Delivery (CN5.3 U8.5), TIDA-010224_Video_Processor_P02_OA7000_Image_Sensor (CN6.E1)
V_VBAT: TIDA-010224_Video_Processor_P01_Power_Delivery (6 pins), TIDA-010224_Video_Processor_P03_CC3235MODA_WIFI_Launchpad (U20.1)

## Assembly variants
001: not fitted C1 C2 C57 C65 C67 C68 C72 C87 C89 C111 C113 C115 C118 C120 C123 C124 C125 FID1 FID2 FID3 R15 R20 R33 R46 R47 R48 R49 R50 R54 R58 R59 R65 R71 R78 R81 R83 R88 R92 R101 R102 R103 R123 R136 R138 R139 R140 R145 R146 R157 R160 R169 R177 U15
